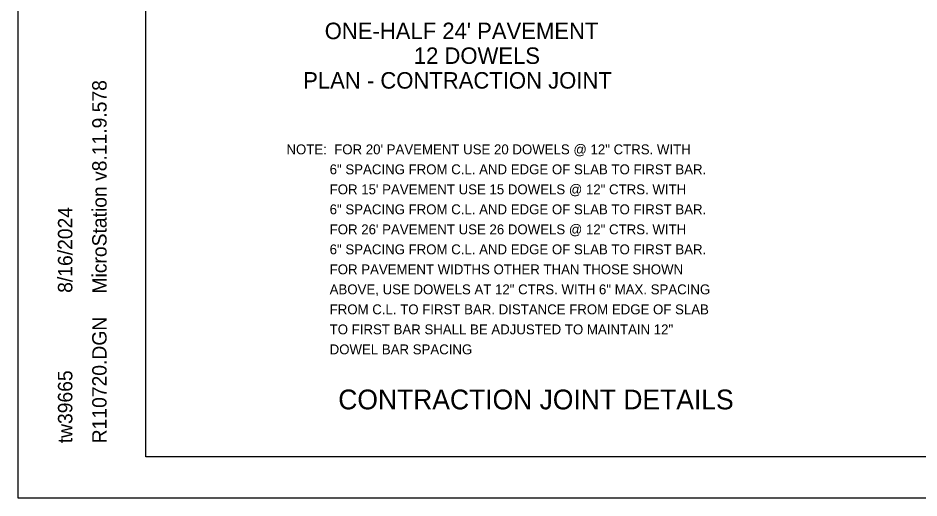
# Model space of a CAD drawing. Extents: x 1375738 to 1375905, y 380661 to 380875.
# Drawn here: x 1375738.22 to 1375781.94, y 380768.06 to 380791.35 of the extents above; entities that cross this region are included whole.
import ezdxf

# ---------------------------------------------------------------- set-up
doc = ezdxf.new("R2010")
doc.units = 0
for name, color, linetype in [('R_Border', 7, 'Continuous'), ('R_Draft', 7, 'Continuous'), ('R_No Plot', 7, 'Continuous')]:
    doc.layers.add(name, color=color, linetype=linetype)

msp = doc.modelspace()

# ---------------------------------------------------------------- linework, layer by layer
at = {"layer": 'R_Border'}
for p, q in [((1375744.419, 380770.053), (1375744.419, 380872.783)), ((1375744.419, 380770.053), (1375744.419, 380770.053)), ((1375902.509, 380770.053), (1375744.419, 380770.053))]:
    msp.add_line(p, q, dxfattribs=at)
at = {"layer": 'R_No Plot'}
msp.add_line((1375738.219, 380768.063), (1375904.885, 380768.063), dxfattribs=at)
for points in [[(1375738.215, 380874.73), (1375904.885, 380874.73), (1375904.885, 380768.061), (1375738.215, 380768.061)], [(1375861.379, 380872.783), (1375871.189, 380872.783), (1375871.189, 380867.843), (1375879.245, 380867.843), (1375890.845, 380867.843), (1375890.845, 380851.508), (1375902.449, 380851.508), (1375902.509, 380770.053), (1375744.419, 380770.053), (1375744.419, 380872.783)]]:
    msp.add_lwpolyline(points, close=True, dxfattribs=at)

# ---------------------------------------------------------------- texts
at = {"layer": 'R_Border'}
for s, p in [('MicroStation v8.11.9.578', (1375742.515, 380777.981)), ('8/16/2024', (1375740.852, 380778.016)), ('R110720.DGN', (1375742.515, 380770.715)), ('tw39665', (1375740.852, 380770.715))]:
    msp.add_text(s, height=0.7, rotation=90, dxfattribs=at).set_placement(p)
at = {"layer": 'R_Draft'}
for s, height, p in [("ONE-HALF 24' PAVEMENT", 0.8, (1375753.098, 380790.323)), ('12 DOWELS', 0.8, (1375757.422, 380789.123)), ('PLAN - CONTRACTION JOINT', 0.8, (1375752.052, 380787.923)), ('NOTE:  FOR 20\' PAVEMENT USE 20 DOWELS @ 12" CTRS. WITH', 0.48, (1375751.24, 380784.736)), (' 6" SPACING FROM C.L. AND EDGE OF SLAB TO FIRST BAR.', 0.48, (1375753.16, 380783.766)), (' FOR 15\' PAVEMENT USE 15 DOWELS @ 12" CTRS. WITH', 0.48, (1375753.16, 380782.795)), (' 6" SPACING FROM C.L. AND EDGE OF SLAB TO FIRST BAR.', 0.48, (1375753.16, 380781.825)), (' FOR 26\' PAVEMENT USE 26 DOWELS @ 12" CTRS. WITH', 0.48, (1375753.16, 380780.854)), (' 6" SPACING FROM C.L. AND EDGE OF SLAB TO FIRST BAR.', 0.48, (1375753.16, 380779.884)), (' FOR PAVEMENT WIDTHS OTHER THAN THOSE SHOWN', 0.48, (1375753.16, 380778.914)), (' ABOVE, USE DOWELS AT 12" CTRS. WITH 6" MAX. SPACING', 0.48, (1375753.16, 380777.943)), (' FROM C.L. TO FIRST BAR. DISTANCE FROM EDGE OF SLAB', 0.48, (1375753.16, 380776.973)), (' TO FIRST BAR SHALL BE ADJUSTED TO MAINTAIN 12" ', 0.48, (1375753.16, 380776.002)), (' DOWEL BAR SPACING ', 0.48, (1375753.16, 380775.032)), ('CONTRACTION JOINT DETAILS', 0.96, (1375753.756, 380772.361))]:
    msp.add_text(s, height=height, dxfattribs=at).set_placement(p)

doc.saveas('drawing.dxf')
